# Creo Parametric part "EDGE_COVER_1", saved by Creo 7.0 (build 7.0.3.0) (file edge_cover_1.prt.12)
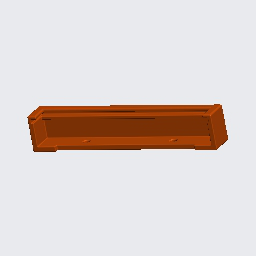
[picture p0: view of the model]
Units: millimeter Kilogram Sec (mmKs); MM, KILOGRAM, SECS

Created from: EDGE_COVER_0.PRT

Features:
  1. coordinate system
  2. datum plane "RIGHT"
  3. datum plane "TOP"
  4. datum plane "FRONT"
  5. protrusion
  6. extruded cut "Extrude 2"
  7. extrusion "Extrude 3"
  8. extrusion "Extrude 4"
  9. extrusion "Extrude 5"
  10. extrusion "Extrude 6"
  11. extrusion "Extrude 7"
  12. cut
  13. chamfer "Chamfer 1"
  14. round "Round 1"
  15. round "Round 2"
  16. round "Round 3"
  17. round "Round 4"
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
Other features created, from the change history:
  round "Round 3" (3 times)
  round "Round 1" (2 times)
  round "Round 2" (2 times)
  chamfer "Chamfer 1"
  component interface "Component Interface id 1752"
  component interface "Component Interface id 1753"
  component interface "Component Interface id 1754"
  component interface "Component Interface id 1755"
  component interface "Component Interface id 1756"
  component interface "Component Interface id 1757"
  round "Round 5"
